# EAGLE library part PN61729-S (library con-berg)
BERG USB connector
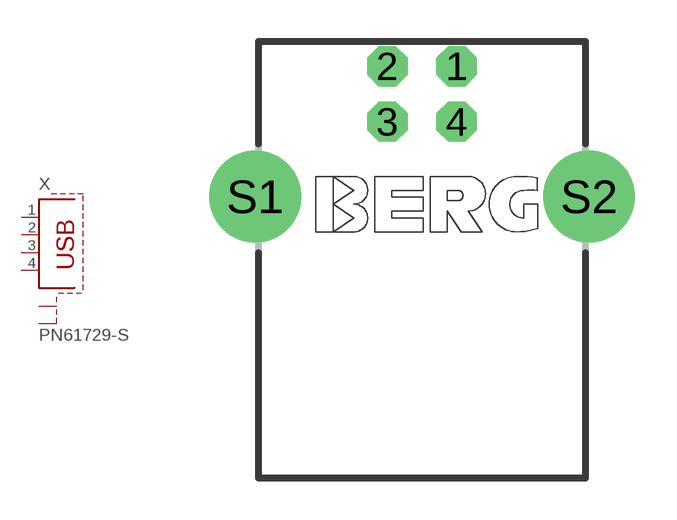
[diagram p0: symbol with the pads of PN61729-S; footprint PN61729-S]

Designator prefix X

## PN61729-S (OC_FARNELL: unknown; OC_NEWARK: unknown)  [PN61729-S]
1  1  pas
2  2  pas
3  3  pas
4  4  pas
S1  S1  pas
S2  S2  pas

## Footprint PN61729-S (pad centres in mm)
USB connector with shield
drill 0.95 octagon: 1 1.25,4.71; 2 -1.25,4.71; 3 -1.25,2.71; 4 1.25,2.71
drill 2.3 pad 2.9 round: S1 -6.02,0; S2 6.02,0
